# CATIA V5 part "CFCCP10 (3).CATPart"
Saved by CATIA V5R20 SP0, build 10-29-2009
Part number: CFCCP10 (3)
Revision: TUTTO
Definition: NON CONOSCIUTO
Nomenclature: CFCCP10 (3)
Source: Unknown
Bounding box of the stored display mesh (mm): x -50 to 50, y -50 to 50, z -40 to 0
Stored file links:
  C:\Users\Utente\Desktop\IO LAVORO\3D X SITO CF\X 3D SITO CF 27-09-2020\CFCCP\CFCCP10 (3).CATPart
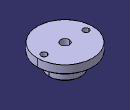
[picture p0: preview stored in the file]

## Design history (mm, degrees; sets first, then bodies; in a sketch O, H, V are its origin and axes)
Body1 "Foro Ø11.0 (11)-1" (main body)
  Solid1: solid without history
